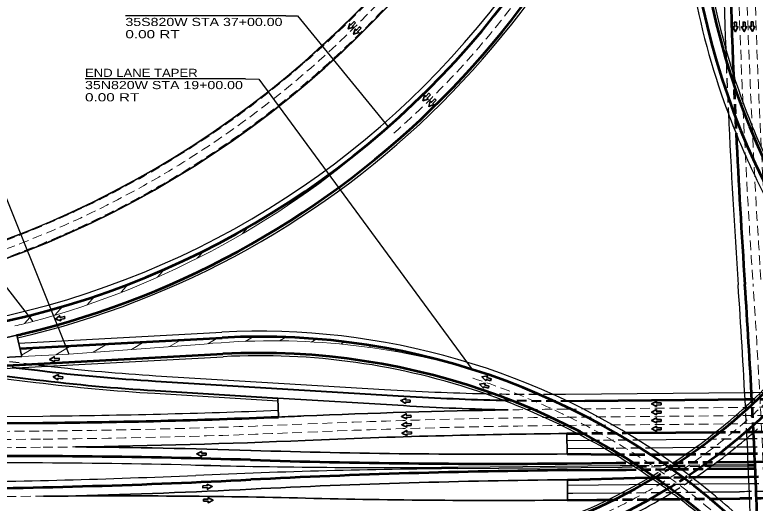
# Model space of a CAD drawing. Extents: x 2326434 to 2368642, y 6985225 to 6995090.
# Drawn here: x 2332211 to 2333302, y 6991238 to 6991957 of the extents above; entities that cross this region are included whole.
import ezdxf

# ---------------------------------------------------------------- set-up
doc = ezdxf.new("R2010")
doc.units = 0
doc.header["$LTSCALE"] = 4.8
doc.linetypes.add('MEDIUM_DASHED', pattern=[4.5, 3, -1.5])
for name, color, linetype, lineweight in [('10', 7, 'Continuous', 35), ('26', 7, 'Continuous', 25), ('27', 7, 'Continuous', 25), ('28', 7, 'Continuous', 25), ('30', 7, 'Continuous', 25), ('40', 7, 'Continuous', 35), ('5', 7, 'Continuous', 25), ('50', 7, 'MEDIUM_DASHED', 13)]:
    doc.layers.add(name, color=color, linetype=linetype, lineweight=lineweight)

msp = doc.modelspace()

# ---------------------------------------------------------------- linework, layer by layer
at = {"layer": '10'}
for p, q in [((2332214.094, 6991485.234), (2332134.678, 6991466.83)), ((2332214.094, 6991485.234), (2332221.36, 6991453.88)), ((2331984.093, 6991441.237), (2332221.36, 6991453.88)), ((2332599.476, 6991364.837), (2332598.364, 6991392.815)), ((2332598.364, 6991392.815), (2332783.342, 6991381.615)), ((2333024.307, 6991340.526), (2333024.587, 6991310.527)), ((2333025.222, 6991242.53), (2333024.942, 6991272.529))]:
    msp.add_line(p, q, dxfattribs=at)
for centre, radius, start, end in [((2331921.237, 6992748.984), 1265.239, 273.05017, 273.05017), ((2333015.029, 6995208.327), 3833.719, 266.53529, 268.84159), ((2333131.363, 6979881.87), 11495.156, 90.96621, 92.46521), ((2332145.585, 7002778.972), 11423.156, 272.27721, 272.46521), ((2333131.363, 6979881.87), 11459.156, 90.53529, 92.46521), ((2332145.585, 7002778.972), 11459.156, 270.7735, 272.46521), ((2332198.613, 6979848.154), 11473.156, 88.20208, 89.49228), ((2332917.662, 7002755.184), 11445.156, 268.20416, 270.53529), ((2333131.867, 6979827.872), 11445.156, 90.53529, 92.86849), ((2331984.949, 7002717.468), 11473.156, 271.57716, 272.86849), ((2332360.37, 6979789.663), 11459.156, 88.60537, 90.53529), ((2332918.166, 7002701.186), 11459.156, 268.60537, 270.53529)]:
    msp.add_arc(centre, radius, start, end, dxfattribs=at)
at = {"layer": '26'}
for p, q in [((2333022.3, 6991398.51), (2333286.464, 6991400.978)), ((2330723.193, 6991352.028), (2332252.211, 6991366.314)), ((2333024.4, 6991330.526), (2333057.944, 6991330.84)), ((2333128.07, 6991331.495), (2333170.679, 6991331.893)), ((2333170.679, 6991331.893), (2333230.357, 6991332.45)), ((2333288.426, 6991332.993), (2333289.757, 6991333.005)), ((2333025.129, 6991252.53), (2333032.653, 6991252.6)), ((2333032.95, 6991252.603), (2333105.099, 6991253.277)), ((2333235.547, 6991254.496), (2333278.725, 6991254.899))]:
    msp.add_line(p, q, dxfattribs=at)
at = {"layer": '26', "linetype": 'MEDIUM_DASHED'}
for p, q in [((2333286.464, 6991400.978), (2333299.089, 6991401.096)), ((2333299.09, 6991401.096), (2333354.86, 6991401.617)), ((2333057.944, 6991330.84), (2333078.374, 6991331.031)), ((2333078.374, 6991331.031), (2333128.07, 6991331.495)), ((2333230.357, 6991332.45), (2333288.494, 6991332.994)), ((2333289.973, 6991333.007), (2333358.12, 6991333.644))]:
    msp.add_line(p, q, dxfattribs=at)
at = {"layer": '26', "lineweight": 53}
for p, q in [((2333050.714, 6991388.775), (2333247.03, 6991390.609)), ((2333247.03, 6991390.609), (2333286.974, 6991390.982)), ((2330723.287, 6991342.029), (2332252.305, 6991356.314)), ((2333024.307, 6991340.526), (2333039.518, 6991340.668)), ((2333025.222, 6991242.53), (2333068.858, 6991242.938)), ((2333068.371, 6991242.933), (2333084.705, 6991243.086)), ((2333162.551, 6991243.813), (2333190.769, 6991244.077)), ((2333247.479, 6991244.607), (2333278.818, 6991244.899))]:
    msp.add_line(p, q, dxfattribs=at)
at = {"layer": '26', "linetype": 'MEDIUM_DASHED', "lineweight": 53}
for p, q in [((2333039.518, 6991340.668), (2333062.373, 6991340.881)), ((2333062.374, 6991340.881), (2333111.992, 6991341.345)), ((2333300.424, 6991343.106), (2333357.781, 6991343.641)), ((2333084.705, 6991243.086), (2333162.551, 6991243.813)), ((2333190.769, 6991244.077), (2333247.479, 6991244.607))]:
    msp.add_line(p, q, dxfattribs=at)
for points in [[(2333286.974, 6991390.982), (2333351.135, 6991391.581), (2333355.321, 6991391.621)], [(2333243.392, 6991342.573), (2333300.105, 6991343.103), (2333300.424, 6991343.106)]]:
    msp.add_lwpolyline(points, dxfattribs=at)
at = {"layer": '26', "lineweight": 53}
msp.add_lwpolyline([(2333111.992, 6991341.345), (2333184.81, 6991342.025), (2333243.392, 6991342.573)], dxfattribs=at)
at = {"layer": '26', "linetype": 'MEDIUM_DASHED'}
msp.add_lwpolyline([(2333105.099, 6991253.277), (2333177.693, 6991253.955), (2333235.547, 6991254.496)], dxfattribs=at)
at = {"layer": '26'}
for centre, radius, start, end in [((2344767.204, 6992339.592), 11517.156, 180.76624, 182.1538), ((2344767.204, 6992339.592), 11517.156, 182.62452, 183.88451), ((2321901.544, 6990786.978), 11401.156, 2.98092, 3.88451), ((2332145.585, 7002778.972), 11413.156, 270.53529, 272.27721), ((2321901.544, 6990786.978), 11401.156, 2.3388, 2.74999), ((2333385.874, 6979786.244), 11469.156, 90.46365, 90.53529), ((2321901.544, 6990786.978), 11401.156, 2.08559, 2.33881)]:
    msp.add_arc(centre, radius, start, end, dxfattribs=at)
at = {"layer": '26', "lineweight": 53}
for centre, radius, start, end in [((2344767.204, 6992339.592), 11507.156, 180.76624, 182.34602), ((2344767.204, 6992339.592), 11507.156, 182.77392, 183.88451), ((2321901.544, 6990786.978), 11411.156, 3.02239, 3.88451), ((2332145.585, 7002778.972), 11423.156, 270.53529, 272.27721), ((2321901.544, 6990786.978), 11411.156, 2.12849, 2.7894), ((2333385.874, 6979786.244), 11459.156, 90.46157, 90.53529)]:
    msp.add_arc(centre, radius, start, end, dxfattribs=at)
at = {"layer": '26', "linetype": 'MEDIUM_DASHED'}
for centre, radius, start, end in [((2344767.204, 6992339.592), 11517.156, 182.1538, 182.62452), ((2321901.544, 6990786.978), 11401.156, 2.75, 2.98092), ((2333385.874, 6979786.244), 11469.156, 90.12362, 90.46365)]:
    msp.add_arc(centre, radius, start, end, dxfattribs=at)
at = {"layer": '26', "linetype": 'MEDIUM_DASHED', "lineweight": 53}
for centre, radius, start, end in [((2344767.204, 6992339.592), 11507.156, 182.34602, 182.77392), ((2321901.544, 6990786.978), 11411.156, 2.7894, 3.02239), ((2333385.874, 6979786.244), 11459.156, 90.12171, 90.46157)]:
    msp.add_arc(centre, radius, start, end, dxfattribs=at)
at = {"layer": '27'}
for p, q in [((2332216.775, 6991473.664), (2332515.807, 6991489.598)), ((2330723.061, 6991358.019), (2332517.722, 6991453.649)), ((2332109.822, 6991431.914), (2332241.947, 6991415.773)), ((2332418.862, 6991425.723), (2332755.774, 6991405.325)), ((2332417.29, 6991399.77), (2332598.523, 6991388.798))]:
    msp.add_line(p, q, dxfattribs=at)
at = {"layer": '27', "lineweight": 53}
for p, q in [((2332218.609, 6991465.75), (2332516.232, 6991481.609)), ((2330723.1, 6991362.027), (2332517.509, 6991457.643))]:
    msp.add_line(p, q, dxfattribs=at)
at = {"layer": '27', "linetype": 'MEDIUM_DASHED', "lineweight": 40}
msp.add_line((2331928.174, 6991472.237), (2332213.18, 6991437.421), dxfattribs=at)
at = {"layer": '27', "linetype": 'MEDIUM_DASHED'}
msp.add_line((2331967.156, 6991475.535), (2332245.106, 6991441.581), dxfattribs=at)
at = {"layer": '27', "lineweight": 40}
for p, q in [((2332132.79, 6991433.137), (2332242.432, 6991419.744)), ((2332213.18, 6991437.421), (2332244.13, 6991433.64)), ((2332418.378, 6991417.737), (2332784.188, 6991395.59)), ((2332417.532, 6991403.763), (2332598.364, 6991392.815))]:
    msp.add_line(p, q, dxfattribs=at)
at = {"layer": '27'}
for centre, radius, start, end in [((2331921.237, 6992748.984), 1265.239, 273.05017, 359.32438), ((2331921.237, 6992748.984), 1301.239, 283.0472, 346.66935), ((2334291.484, 6992197.218), 1099.348, 179.32439, 199.55249), ((2334291.484, 6992197.218), 1073.348, 179.32439, 195.11064), ((2334291.484, 6992197.218), 1073.348, 195.11064, 198.74253), ((2334291.484, 6992197.218), 1073.348, 198.74253, 204.79099), ((2334291.484, 6992197.218), 1099.348, 199.55249, 202.69404), ((2334291.484, 6992197.218), 1099.348, 202.69404, 208.14794), ((2332571.664, 6990441.344), 1049.741, 54.63414, 93.05017), ((2332571.664, 6990441.344), 1013.741, 70.89721, 93.05017), ((2332591.508, 6994277.29), 2856.789, 263.3226, 266.53529), ((2332713.439, 6992011.577), 853.473, 313.22856, 317.07975), ((2332591.508, 6994277.29), 2882.789, 263.03529, 266.53529), ((2332986.614, 6995218.062), 3819.719, 266.53529, 268.75257), ((2332571.664, 6990441.344), 1013.741, 55.61393, 70.89721), ((2332986.614, 6995218.062), 3819.719, 270.25256, 270.53529), ((2332713.439, 6992011.577), 853.473, 311.85153, 313.22856), ((2332713.439, 6992011.577), 853.473, 303.13396, 311.85153), ((2332713.439, 6992011.577), 889.473, 310.05379, 311.70652), ((2332713.439, 6992011.577), 889.473, 303.99424, 310.05379), ((2332571.664, 6990441.344), 1049.741, 54.49447, 54.63414), ((2332571.664, 6990441.344), 1049.741, 54.44558, 54.49447), ((2332571.664, 6990441.344), 1049.741, 54.26356, 54.44558), ((2332571.664, 6990441.344), 1049.741, 53.16327, 54.26356), ((2332571.664, 6990441.344), 1049.741, 52.83731, 53.16327), ((2332713.439, 6992011.577), 853.473, 284.8512, 300.50378), ((2332571.664, 6990441.344), 1013.741, 55.05618, 55.61393), ((2332571.664, 6990441.344), 1013.741, 53.8631, 55.05618), ((2332571.664, 6990441.344), 1049.741, 52.60817, 52.83731), ((2332571.664, 6990441.344), 1049.741, 52.35173, 52.60817), ((2332571.664, 6990441.344), 1049.741, 46.70366, 52.35173), ((2332571.664, 6990441.344), 1013.741, 52.93561, 53.8631), ((2332713.439, 6992011.577), 889.473, 293.78263, 301.52289), ((2332571.664, 6990441.344), 1013.741, 44.802, 52.93561)]:
    msp.add_arc(centre, radius, start, end, dxfattribs=at)
at = {"layer": '27', "lineweight": 53}
for centre, radius, start, end in [((2331921.237, 6992748.984), 1273.239, 273.05017, 359.32438), ((2331921.237, 6992748.984), 1297.239, 283.52851, 346.66935), ((2334291.484, 6992197.218), 1091.348, 179.32439, 270.28461), ((2334291.484, 6992197.218), 1077.348, 179.32439, 270.28461), ((2332713.439, 6992011.577), 857.473, 303.23828, 325.54536), ((2332713.439, 6992011.577), 881.473, 303.81771, 325.06048), ((2331921.237, 6992748.984), 1297.239, 283.0472, 283.52851), ((2332571.664, 6990441.344), 1041.741, 359.3366, 93.05017), ((2332571.664, 6990441.344), 1017.741, 359.3366, 93.05017), ((2332713.439, 6992011.577), 857.473, 269.30964, 300.62739), ((2332713.439, 6992011.577), 881.473, 269.30964, 301.31395)]:
    msp.add_arc(centre, radius, start, end, dxfattribs=at)
at = {"layer": '27', "lineweight": 40}
for centre, radius, start, end in [((2332591.508, 6994277.29), 2864.789, 263.03529, 266.53529), ((2332591.508, 6994277.29), 2878.789, 263.03529, 266.53529), ((2333015.029, 6995208.327), 3819.719, 266.53529, 268.70779), ((2333015.029, 6995208.327), 3819.719, 270.13526, 270.53529)]:
    msp.add_arc(centre, radius, start, end, dxfattribs=at)
at = {"layer": '27', "linetype": 'MEDIUM_DASHED'}
for centre, radius, start, end in [((2332591.508, 6994277.29), 2856.789, 263.03529, 263.3226), ((2332986.614, 6995218.062), 3819.719, 268.75257, 270.25256), ((2332713.439, 6992011.577), 853.473, 300.50378, 303.13396), ((2332713.439, 6992011.577), 889.473, 301.52289, 303.99424)]:
    msp.add_arc(centre, radius, start, end, dxfattribs=at)
at = {"layer": '27', "linetype": 'MEDIUM_DASHED', "lineweight": 40}
msp.add_arc((2333015.029, 6995208.327), 3819.719, 268.70779, 270.13526, dxfattribs=at)
at = {"layer": '27', "linetype": 'MEDIUM_DASHED', "lineweight": 53}
for radius, start, end in [(857.473, 300.62739, 303.23828), (881.473, 301.31395, 303.81771)]:
    msp.add_arc((2332713.439, 6992011.577), radius, start, end, dxfattribs=at)
at = {"layer": '28'}
for radius, start in [(1431.895, 270.53549), (1432.395, 270.53549), (1458.395, 271.68649), (1458.895, 271.68649)]:
    msp.add_arc((2331697.424, 6992968.484), radius, start, 359.76624, dxfattribs=at)
at = {"layer": '30'}
for p, q in [((2333024.512, 6991318.527), (2333078.94, 6991319.035)), ((2333146.559, 6991319.667), (2333213.988, 6991320.297)), ((2333273.857, 6991320.856), (2333290.296, 6991321.01)), ((2332863.39, 6991291.02), (2333102.752, 6991293.257)), ((2332863.408, 6991289.02), (2333105.734, 6991291.284)), ((2333236.991, 6991292.511), (2333291.505, 6991293.02)), ((2333239.762, 6991294.537), (2333291.421, 6991295.019)), ((2333025.017, 6991264.529), (2333161.525, 6991265.805)), ((2333220.747, 6991266.358), (2333292.566, 6991267.029))]:
    msp.add_line(p, q, dxfattribs=at)
at = {"layer": '30', "linetype": 'MEDIUM_DASHED'}
for p, q in [((2333078.94, 6991319.035), (2333096.853, 6991319.203)), ((2333096.853, 6991319.203), (2333146.559, 6991319.667)), ((2333213.988, 6991320.297), (2333273.857, 6991320.856)), ((2333290.296, 6991321.01), (2333358.792, 6991321.65)), ((2333102.752, 6991293.257), (2333109.474, 6991293.319)), ((2333105.734, 6991291.284), (2333183.911, 6991292.015)), ((2333109.475, 6991293.319), (2333181.155, 6991293.989)), ((2333183.911, 6991292.015), (2333236.991, 6991292.511)), ((2333291.421, 6991295.019), (2333301.609, 6991295.115)), ((2333291.505, 6991293.02), (2333301.865, 6991293.117)), ((2333161.525, 6991265.805), (2333220.747, 6991266.358)), ((2333292.566, 6991267.029), (2333361.653, 6991267.674))]:
    msp.add_line(p, q, dxfattribs=at)
at = {"layer": '30', "lineweight": 53}
for p, q in [((2333024.587, 6991310.527), (2333094.625, 6991309.781)), ((2333161.352, 6991309.805), (2333199.685, 6991310.163)), ((2333261.149, 6991310.737), (2333290.735, 6991311.014)), ((2333024.718, 6991296.528), (2333096.723, 6991297.2)), ((2333245.238, 6991298.588), (2333291.251, 6991299.018)), ((2333024.811, 6991286.528), (2333099.363, 6991287.225)), ((2333099.468, 6991287.226), (2333111.635, 6991287.339)), ((2333231.379, 6991288.458), (2333291.672, 6991289.021)), ((2333213.962, 6991276.295), (2333292.165, 6991277.026))]:
    msp.add_line(p, q, dxfattribs=at)
at = {"layer": '30', "linetype": 'MEDIUM_DASHED', "lineweight": 53}
for p, q in [((2333094.625, 6991309.781), (2333124.601, 6991309.461)), ((2333124.601, 6991309.461), (2333161.352, 6991309.805)), ((2333199.685, 6991310.163), (2333261.149, 6991310.737)), ((2333290.735, 6991311.014), (2333359.467, 6991311.656)), ((2333096.723, 6991297.2), (2333116.774, 6991297.388)), ((2333116.775, 6991297.388), (2333159.639, 6991297.788)), ((2333159.639, 6991297.788), (2333245.238, 6991298.588)), ((2333291.251, 6991299.018), (2333301.56, 6991299.114)), ((2333301.56, 6991299.114), (2333360.098, 6991299.661)), ((2333111.635, 6991287.339), (2333188.794, 6991288.06)), ((2333188.795, 6991288.06), (2333231.379, 6991288.458)), ((2333291.672, 6991289.021), (2333302.258, 6991289.12)), ((2333160.301, 6991275.794), (2333213.962, 6991276.295)), ((2333292.165, 6991277.026), (2333361.377, 6991277.672))]:
    msp.add_line(p, q, dxfattribs=at)
at = {"layer": '30', "linetype": 'MEDIUM_DASHED'}
msp.add_lwpolyline([(2333181.155, 6991293.989), (2333183.959, 6991294.015), (2333239.762, 6991294.537)], dxfattribs=at)
at = {"layer": '30', "lineweight": 53}
msp.add_lwpolyline([(2333024.942, 6991272.529), (2333124.919, 6991275.463), (2333145.687, 6991275.657)], dxfattribs=at)
at = {"layer": '30', "linetype": 'MEDIUM_DASHED', "lineweight": 53}
msp.add_lwpolyline([(2333145.687, 6991275.657), (2333147.46, 6991275.674), (2333159.896, 6991275.79)], dxfattribs=at)
at = {"layer": '30', "lineweight": 53}
for centre, start, end in [((2332198.613, 6979848.154), 88.20208, 90.53529), ((2332917.662, 7002755.184), 268.20208, 270.53529), ((2333131.867, 6979827.872), 90.53529, 92.86849), ((2331984.949, 7002717.468), 270.53529, 272.86849)]:
    msp.add_arc(centre, 11459.156, start, end, dxfattribs=at)
at = {"layer": '30'}
for centre, radius, start, end in [((2332198.613, 6979848.154), 11449.156, 88.20208, 90.53529), ((2332756.334, 7002749.676), 11459.156, 268.60495, 270.53529), ((2332970.465, 6979830.365), 11459.156, 90.53529, 92.46562), ((2331984.949, 7002717.468), 11449.156, 270.53529, 272.46562)]:
    msp.add_arc(centre, radius, start, end, dxfattribs=at)
at = {"layer": '40'}
for points in [[(2332712.921, 6991944.98), (2332710.758, 6991947.06), (2332706.04, 6991942.154), (2332704.283, 6991943.844), (2332702.016, 6991936.034), (2332709.731, 6991938.605), (2332708.203, 6991940.074)], [(2333273.876, 6991946.068), (2333270.878, 6991945.95), (2333271.146, 6991939.149), (2333268.711, 6991939.052), (2333272.771, 6991932.007), (2333276.263, 6991939.35), (2333274.145, 6991939.267)], [(2333286.674, 6991946.239), (2333283.675, 6991946.121), (2333283.944, 6991939.32), (2333281.508, 6991939.224), (2333285.568, 6991932.178), (2333289.06, 6991939.522), (2333286.942, 6991939.438)], [(2333298.58, 6991946.595), (2333295.582, 6991946.477), (2333295.851, 6991939.676), (2333293.415, 6991939.58), (2333297.475, 6991932.534), (2333300.967, 6991939.878), (2333298.849, 6991939.794)], [(2332720.969, 6991937.12), (2332718.806, 6991939.199), (2332714.088, 6991934.293), (2332712.331, 6991935.983), (2332710.064, 6991928.174), (2332717.779, 6991930.744), (2332716.251, 6991932.213)], [(2332823.081, 6991839.343), (2332820.918, 6991841.423), (2332816.2, 6991836.517), (2332814.443, 6991838.206), (2332812.176, 6991830.397), (2332819.891, 6991832.968), (2332818.363, 6991834.437)], [(2332831.616, 6991831.072), (2332829.453, 6991833.152), (2332824.735, 6991828.246), (2332822.978, 6991829.935), (2332820.711, 6991822.126), (2332828.425, 6991824.697), (2332826.898, 6991826.166)], [(2332284.799, 6991510.028), (2332284.173, 6991512.963), (2332277.516, 6991511.542), (2332277.007, 6991513.926), (2332270.754, 6991508.728), (2332278.584, 6991506.535), (2332278.142, 6991508.608)], [(2332276.274, 6991448.652), (2332276.094, 6991451.647), (2332269.299, 6991451.239), (2332269.153, 6991453.672), (2332262.193, 6991449.468), (2332269.607, 6991446.128), (2332269.479, 6991448.244)], [(2332281.324, 6991421.238), (2332281.612, 6991424.225), (2332274.837, 6991424.878), (2332275.071, 6991427.304), (2332267.541, 6991424.234), (2332274.345, 6991419.782), (2332274.549, 6991421.892)], [(2332911.924, 6991418.094), (2332912.86, 6991420.945), (2332906.392, 6991423.067), (2332907.152, 6991425.382), (2332899.132, 6991424.036), (2332904.796, 6991418.201), (2332905.457, 6991420.215)], [(2332908.494, 6991407.33), (2332909.429, 6991410.181), (2332902.962, 6991412.303), (2332903.722, 6991414.618), (2332895.702, 6991413.272), (2332901.366, 6991407.437), (2332902.027, 6991409.451)], [(2332793.31, 6991386.515), (2332793.488, 6991389.51), (2332786.693, 6991389.913), (2332786.837, 6991392.346), (2332779.426, 6991388.999), (2332786.39, 6991384.801), (2332786.516, 6991386.917)], [(2333162.915, 6991382.608), (2333162.868, 6991385.608), (2333156.062, 6991385.501), (2333156.023, 6991387.938), (2333148.884, 6991384.046), (2333156.143, 6991380.381), (2333156.109, 6991382.5)], [(2332794.61, 6991364.423), (2332794.502, 6991367.422), (2332787.7, 6991367.178), (2332787.613, 6991369.614), (2332780.552, 6991365.581), (2332787.883, 6991362.061), (2332787.807, 6991364.18)], [(2333162.997, 6991370.494), (2333162.949, 6991373.494), (2333156.143, 6991373.387), (2333156.105, 6991375.824), (2333148.965, 6991371.932), (2333156.224, 6991368.267), (2333156.191, 6991370.387)], [(2332794.933, 6991352.313), (2332794.826, 6991355.312), (2332788.023, 6991355.069), (2332787.936, 6991357.505), (2332780.876, 6991353.471), (2332788.206, 6991349.952), (2332788.131, 6991352.07)], [(2333163.078, 6991358.38), (2333163.031, 6991361.381), (2333156.225, 6991361.273), (2333156.186, 6991363.71), (2333149.047, 6991359.819), (2333156.306, 6991356.154), (2333156.272, 6991358.273)], [(2332795.308, 6991339.934), (2332795.201, 6991342.933), (2332788.399, 6991342.69), (2332788.312, 6991345.125), (2332781.251, 6991341.092), (2332788.582, 6991337.573), (2332788.506, 6991339.691)], [(2333163.206, 6991345.996), (2333163.159, 6991348.996), (2333156.353, 6991348.889), (2333156.315, 6991351.326), (2333149.175, 6991347.434), (2333156.434, 6991343.769), (2333156.4, 6991345.889)], [(2332492.828, 6991308.536), (2332492.901, 6991311.536), (2332486.096, 6991311.702), (2332486.155, 6991314.138), (2332478.866, 6991310.535), (2332485.972, 6991306.583), (2332486.023, 6991308.702)], [(2332487.677, 6991263.668), (2332487.767, 6991260.669), (2332494.571, 6991260.872), (2332494.644, 6991258.436), (2332501.728, 6991262.428), (2332494.418, 6991265.99), (2332494.481, 6991263.871)], [(2332488.942, 6991244.112), (2332488.903, 6991241.111), (2332495.71, 6991241.024), (2332495.678, 6991238.587), (2332502.926, 6991242.274), (2332495.775, 6991246.144), (2332495.748, 6991244.025)]]:
    msp.add_lwpolyline(points, close=True, dxfattribs=at)
at = {"layer": '5'}
for p, q in [((2332610.009, 6991955.395), (2332373.855, 6991955.395)), ((2332550.549, 6991862.499), (2332314.395, 6991862.499))]:
    msp.add_line(p, q, dxfattribs=at)
for points in [[(2332610.009, 6991955.395), (2332627.552, 6991955.395), (2332760.87, 6991791.824)], [(2332550.549, 6991862.499), (2332570.39, 6991862.359), (2332884.584, 6991434.976)], [(2332162.102, 6991752.381), (2332171.82, 6991752.241), (2332290.477, 6991457.563)], [(2332081.854, 6991688.943), (2332094.392, 6991688.943), (2332237.277, 6991505.271)]]:
    msp.add_lwpolyline(points, dxfattribs=at)
at = {"layer": '50', "linetype": 'Continuous'}
for p, q in [((2332730.033, 6991764.871), (2332733.613, 6991768.853)), ((2332623.547, 6991683.796), (2332631.133, 6991692.236)), ((2332545.703, 6991634.587), (2332554.604, 6991644.49)), ((2332479.73, 6991598.586), (2332490.176, 6991610.208)), ((2332421.077, 6991570.728), (2332432.007, 6991582.889)), ((2332367.434, 6991548.445), (2332378.539, 6991560.8)), ((2332317.315, 6991530.083), (2332328.707, 6991542.757)), ((2332270.019, 6991514.86), (2332281.763, 6991527.926)), ((2332225.134, 6991502.322), (2332237.158, 6991515.699)), ((2332438.984, 6991468.458), (2332455.824, 6991478.39)), ((2332495.196, 6991472.588), (2332509.92, 6991481.273)), ((2332550.286, 6991476.057), (2332561.875, 6991482.893)), ((2332600.694, 6991476.765), (2332610.029, 6991482.271)), ((2332647.377, 6991475.275), (2332654.782, 6991479.643)), ((2332220.888, 6991455.916), (2332239.442, 6991466.86)), ((2332271.141, 6991456.532), (2332293.538, 6991469.743)), ((2332290.477, 6991457.563), (2332489.981, 6991472.199)), ((2332326.588, 6991460.212), (2332347.633, 6991472.625)), ((2332382.786, 6991464.335), (2332401.729, 6991475.508)), ((2332691.031, 6991472), (2332696.757, 6991475.377)), ((2332732.177, 6991467.244), (2332736.422, 6991469.747)), ((2332221.36, 6991453.88), (2332290.477, 6991457.563)), ((2332771.209, 6991461.242), (2332774.132, 6991462.965)), ((2332808.431, 6991454.171), (2332810.167, 6991455.195)), ((2332843.599, 6991445.89), (2332844.749, 6991446.568)), ((2332877.578, 6991436.907), (2332877.701, 6991436.979))]:
    msp.add_line(p, q, dxfattribs=at)
at = {"layer": '50'}
for p, q in [((2333024.082, 6991364.525), (2333577.548, 6991369.696)), ((2333024.195, 6991352.525), (2333577.66, 6991357.696)), ((2332124.243, 6991343.117), (2332252.417, 6991344.315)), ((2329664.221, 6991308.133), (2332252.529, 6991332.315)), ((2329664.333, 6991296.134), (2332252.641, 6991320.316))]:
    msp.add_line(p, q, dxfattribs=at)
at = {"layer": '50', "linetype": 'Continuous'}
msp.add_lwpolyline([(2332516.232, 6991481.609), (2332218.609, 6991465.75), (2332221.36, 6991453.88), (2332290.477, 6991457.563), (2332489.981, 6991472.199)], dxfattribs=at)
at = {"layer": '50'}
for points in [[(2333023.97, 6991376.524), (2333286.29, 6991378.975), (2333577.436, 6991381.695)], [(2329665.005, 6991224.137), (2332090.455, 6991246.797), (2332253.314, 6991248.319)]]:
    msp.add_lwpolyline(points, dxfattribs=at)
for centre, radius, start, end in [((2331697.424, 6992968.484), 1433.395, 270.53549, 359.76624), ((2331697.424, 6992968.484), 1445.395, 270.53549, 359.76624), ((2331697.424, 6992968.484), 1457.395, 271.68649, 359.76624), ((2331921.237, 6992748.984), 1285.675, 311.25764, 359.32438), ((2344767.204, 6992339.592), 11495.156, 180.76624, 183.88451), ((2344767.204, 6992339.592), 11483.156, 180.76624, 183.88451), ((2344767.204, 6992339.592), 11471.156, 180.76624, 183.88451), ((2332713.439, 6992011.577), 869.473, 269.30964, 347.69841), ((2321901.544, 6990786.978), 11423.156, 1.58947, 3.88451), ((2332571.664, 6990441.344), 1029.741, 359.3366, 72.51947), ((2333131.363, 6979881.87), 11495.156, 90.53529, 90.96621), ((2333131.363, 6979881.87), 11483.156, 90.53529, 92.46521), ((2332145.585, 7002778.972), 11435.156, 270.53529, 272.46521), ((2333131.363, 6979881.87), 11471.156, 90.53529, 92.46521), ((2332145.585, 7002778.972), 11447.156, 270.53529, 272.46521), ((2332145.585, 7002778.972), 11459.156, 270.53529, 270.7735)]:
    msp.add_arc(centre, radius, start, end, dxfattribs=at)
at = {"layer": '50', "linetype": 'Continuous'}
for centre, radius, start, end in [((2331921.237, 6992748.984), 1273.239, 273.05017, 311.25764), ((2331902.284, 6992739.009), 1278.409, 285.19108, 312.19108), ((2331921.237, 6992748.984), 1283.239, 283.04721, 284.25764), ((2332590.723, 6990429.94), 1047.116, 73.70167, 95.52089), ((2332590.723, 6990429.94), 1047.116, 73.70167, 95.52089), ((2332571.664, 6990441.344), 1041.741, 72.51947, 93.05017)]:
    msp.add_arc(centre, radius, start, end, dxfattribs=at)

# ---------------------------------------------------------------- texts
at = {"layer": '5'}
for s, width, p in [('35S820W STA 37+00.00', 1.3, (2332373.854, 6991940.395)), ('0.00 RT', 1.4, (2332373.855, 6991922.395)), ('END LANE TAPER', 1.2, (2332314.394, 6991865.499)), ('35N820W STA 19+00.00', 1.3, (2332314.394, 6991847.499)), ('0.00 RT', 1.4, (2332314.395, 6991829.499))]:
    msp.add_text(s, height=12, dxfattribs=dict(at, width=width)).set_placement(p)

doc.saveas('drawing.dxf')
